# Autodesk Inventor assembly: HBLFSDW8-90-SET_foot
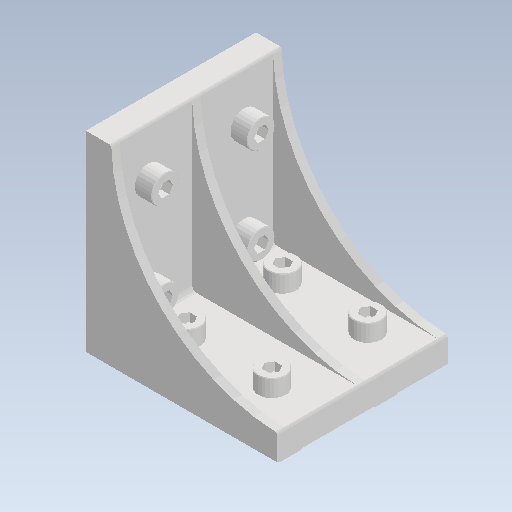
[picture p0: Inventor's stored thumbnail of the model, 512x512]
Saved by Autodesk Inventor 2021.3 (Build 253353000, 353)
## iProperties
Created: 2022-02
Part Number: HBLFSDW8-90-SET_foot
Document SubType Name: Assembly
Designer: kengo
Author: kengo
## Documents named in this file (4)
- C:\Users\kengo\Documents\S2S_frame\SDC345\frame_misumi_ver9\HBLFSDW8-90-SET_foot.iam
- C:\Users\kengo\Documents\S2S_frame\SDC345\frame_misumi_ver9\HBLFSDW8-90.ipt
- C:\Users\kengo\Documents\S2S_frame\SDC345\frame_misumi_ver9\HNTT8-8.ipt
- C:\Users\kengo\Documents\S2S_frame\SDC345\frame_misumi_ver9\SCB8-22.ipt
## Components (13 placed, 3 different names)
1. HBLFSDW8-90
2. SCB8-22
3. SCB8-22:1
4. SCB8-22:2
5. SCB8-22:3
6. HNTT8-8:4
7. SCB8-22:4
8. HNTT8-8:5
9. SCB8-22:5
10. HNTT8-8:6
11. SCB8-22:6
12. HNTT8-8:7
13. SCB8-22:7
